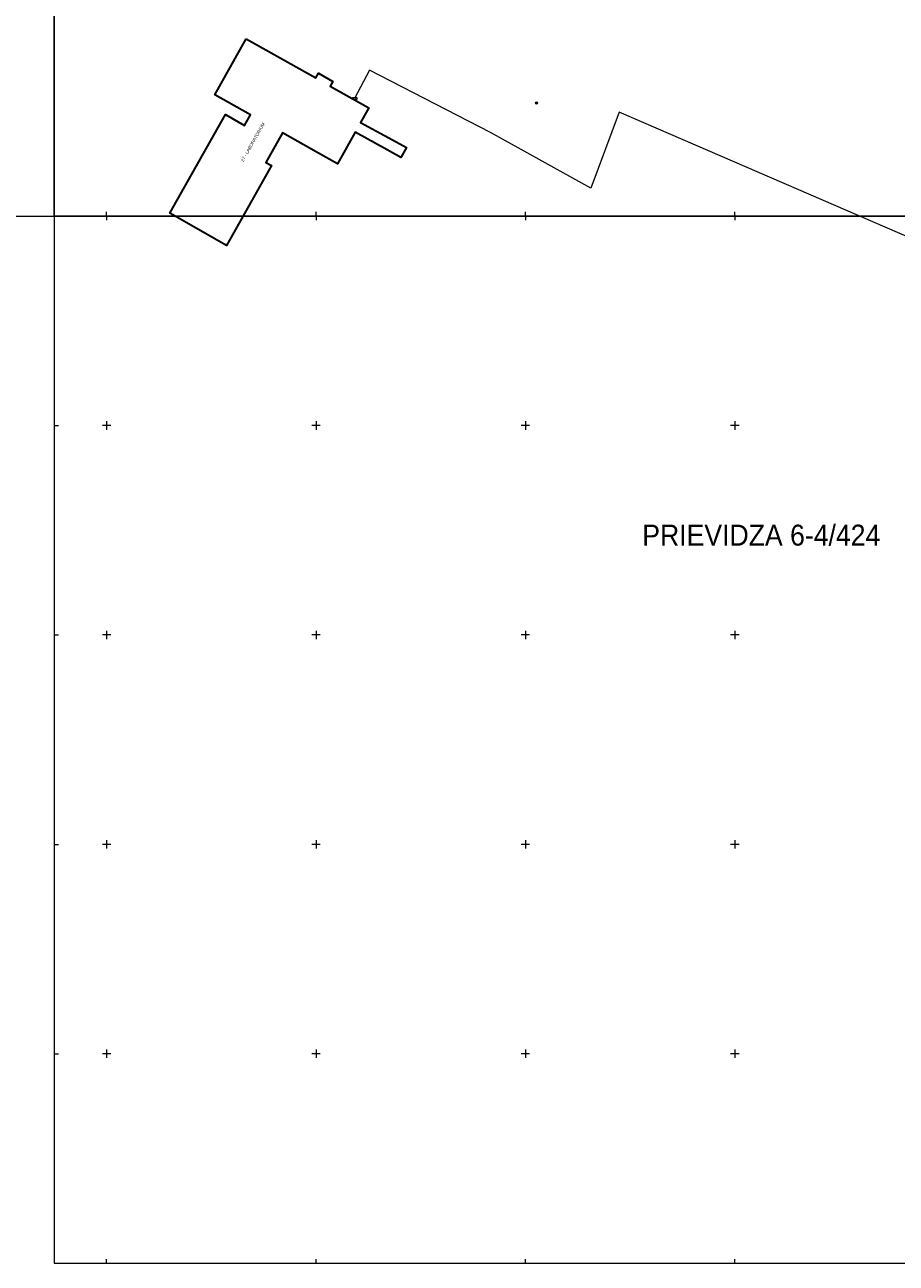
# Model space of a CAD drawing. Extents: x -46688 to -46438, y -123000 to -122825.
# Drawn here: x -46531.95 to -46511.15, y -122950 to -122920.43 of the extents above; entities that cross this region are included whole.
import ezdxf
from ezdxf.enums import TextEntityAlignment as Align

# ---------------------------------------------------------------- set-up
doc = ezdxf.new("R2010")
doc.units = 0
doc.header["$LTSCALE"] = 0.2
for name, color, linetype, lineweight in [('17', 7, 'Continuous', 13), ('18', 7, 'Continuous', 13), ('48', 7, 'Continuous', 13), ('8', 7, 'Continuous', 35)]:
    doc.layers.add(name, color=color, linetype=linetype, lineweight=lineweight)
doc.layers.add('19', color=7, linetype='Continuous')
doc.layers.add('29', color=7, linetype='Continuous')

msp = doc.modelspace()

# ---------------------------------------------------------------- linework, layer by layer
at = {"layer": '17'}
for points in [[(-46531.25, -122900), (-46562.5, -122900), (-46562.5, -122925), (-46531.25, -122925)], [(-46500, -122900), (-46531.25, -122900), (-46531.25, -122925), (-46500, -122925)], [(-46500, -122925), (-46531.25, -122925), (-46531.25, -122950), (-46500, -122950)]]:
    msp.add_lwpolyline(points, close=True, dxfattribs=at)
for radius in [0.025, 0.02, 0.015, 0.01, 0.005]:
    msp.add_circle((-46519.735, -122922.3), radius, dxfattribs=at)
at = {"layer": '18'}
for p, q in [((-46530, -122925), (-46530, -122924.9)), ((-46530, -122925), (-46530, -122924.9)), ((-46530, -122925), (-46530, -122924.9)), ((-46530, -122925), (-46530, -122924.9)), ((-46530, -122925), (-46530, -122925.1)), ((-46530, -122925), (-46530, -122925.1)), ((-46530, -122925), (-46530, -122925.1)), ((-46530, -122925), (-46530, -122925.1)), ((-46525, -122925), (-46525, -122924.9)), ((-46525, -122925), (-46525, -122924.9)), ((-46525, -122925), (-46525, -122924.9)), ((-46525, -122925), (-46525, -122924.9)), ((-46525, -122925), (-46525, -122925.1)), ((-46525, -122925), (-46525, -122925.1)), ((-46525, -122925), (-46525, -122925.1)), ((-46525, -122925), (-46525, -122925.1)), ((-46520, -122925), (-46520, -122924.9)), ((-46520, -122925), (-46520, -122924.9)), ((-46520, -122925), (-46520, -122924.9)), ((-46520, -122925), (-46520, -122924.9)), ((-46520, -122925), (-46520, -122925.1)), ((-46520, -122925), (-46520, -122925.1)), ((-46520, -122925), (-46520, -122925.1)), ((-46520, -122925), (-46520, -122925.1)), ((-46515, -122925), (-46515, -122924.9)), ((-46515, -122925), (-46515, -122924.9)), ((-46515, -122925), (-46515, -122924.9)), ((-46515, -122925), (-46515, -122924.9)), ((-46515, -122925), (-46515, -122925.1)), ((-46515, -122925), (-46515, -122925.1)), ((-46515, -122925), (-46515, -122925.1)), ((-46515, -122925), (-46515, -122925.1)), ((-46531.25, -122930), (-46531.15, -122930)), ((-46529.9, -122930), (-46530.1, -122930)), ((-46530, -122929.9), (-46530, -122930.1)), ((-46524.9, -122930), (-46525.1, -122930)), ((-46525, -122929.9), (-46525, -122930.1)), ((-46519.9, -122930), (-46520.1, -122930)), ((-46520, -122929.9), (-46520, -122930.1)), ((-46514.9, -122930), (-46515.1, -122930)), ((-46515, -122929.9), (-46515, -122930.1)), ((-46531.25, -122935), (-46531.15, -122935)), ((-46529.9, -122935), (-46530.1, -122935)), ((-46530, -122934.9), (-46530, -122935.1)), ((-46524.9, -122935), (-46525.1, -122935)), ((-46525, -122934.9), (-46525, -122935.1)), ((-46519.9, -122935), (-46520.1, -122935)), ((-46520, -122934.9), (-46520, -122935.1)), ((-46514.9, -122935), (-46515.1, -122935)), ((-46515, -122934.9), (-46515, -122935.1)), ((-46531.25, -122940), (-46531.15, -122940)), ((-46529.9, -122940), (-46530.1, -122940)), ((-46530, -122939.9), (-46530, -122940.1)), ((-46524.9, -122940), (-46525.1, -122940)), ((-46525, -122939.9), (-46525, -122940.1)), ((-46519.9, -122940), (-46520.1, -122940)), ((-46520, -122939.9), (-46520, -122940.1)), ((-46514.9, -122940), (-46515.1, -122940)), ((-46515, -122939.9), (-46515, -122940.1)), ((-46530, -122944.9), (-46530, -122945.1)), ((-46525, -122944.9), (-46525, -122945.1)), ((-46520, -122944.9), (-46520, -122945.1)), ((-46515, -122944.9), (-46515, -122945.1)), ((-46531.25, -122945), (-46531.15, -122945)), ((-46529.9, -122945), (-46530.1, -122945)), ((-46524.9, -122945), (-46525.1, -122945)), ((-46519.9, -122945), (-46520.1, -122945)), ((-46514.9, -122945), (-46515.1, -122945)), ((-46530, -122950), (-46530, -122949.9)), ((-46530, -122950), (-46530, -122949.9)), ((-46530, -122950), (-46530, -122949.9)), ((-46530, -122950), (-46530, -122949.9)), ((-46525, -122950), (-46525, -122949.9)), ((-46525, -122950), (-46525, -122949.9)), ((-46525, -122950), (-46525, -122949.9)), ((-46525, -122950), (-46525, -122949.9)), ((-46520, -122950), (-46520, -122949.9)), ((-46520, -122950), (-46520, -122949.9)), ((-46520, -122950), (-46520, -122949.9)), ((-46520, -122950), (-46520, -122949.9)), ((-46515, -122950), (-46515, -122949.9)), ((-46515, -122950), (-46515, -122949.9)), ((-46515, -122950), (-46515, -122949.9)), ((-46515, -122950), (-46515, -122949.9))]:
    msp.add_line(p, q, dxfattribs=at)
at = {"layer": '48'}
msp.add_lwpolyline([(-46496.57, -122935.641), (-46496.589, -122935.69), (-46496.722, -122935.624), (-46496.075, -122934.164), (-46495.316, -122932.644), (-46498.427, -122931.143), (-46501.675, -122929.63), (-46506.239, -122927.503), (-46517.763, -122922.516), (-46518.437, -122924.33), (-46520.833, -122923.001), (-46523.724, -122921.515), (-46524.079, -122922.19)], dxfattribs=at)
msp.add_lwpolyline([(-46524.128, -122922.165), (-46524.029, -122922.165), (-46524.029, -122922.215), (-46524.128, -122922.215)], close=True, dxfattribs=at)
at = {"layer": '8'}
msp.add_lwpolyline([(-46526.668, -122920.765), (-46525.006, -122921.701), (-46524.943, -122921.588), (-46524.596, -122921.783), (-46524.662, -122921.895), (-46524.006, -122922.265), (-46523.74, -122922.419), (-46523.937, -122922.768), (-46523.17, -122923.18), (-46522.842, -122923.36), (-46522.972, -122923.599), (-46523.302, -122923.418), (-46524.068, -122922.998), (-46524.491, -122923.751), (-46524.758, -122923.604), (-46525.803, -122923.014), (-46526.197, -122923.717), (-46526.065, -122923.793), (-46527.14, -122925.699), (-46528.489, -122924.927), (-46527.165, -122922.576), (-46526.704, -122922.836), (-46526.563, -122922.584), (-46527.418, -122922.105)], close=True, dxfattribs=at)

# ---------------------------------------------------------------- texts
at = {"layer": '19', "width": 0.95}
msp.add_text('PRIEVIDZA 6-4/424', height=0.5, dxfattribs=at).set_placement((-46514.368, -122932.867), align=Align.CENTER)
at = {"layer": '29', "width": 1.05}
msp.add_text('27 - LABORATORIUM', height=0.075, rotation=60.659, dxfattribs=at).set_placement((-46526.476, -122923.254), align=Align.CENTER)

doc.saveas('drawing.dxf')
